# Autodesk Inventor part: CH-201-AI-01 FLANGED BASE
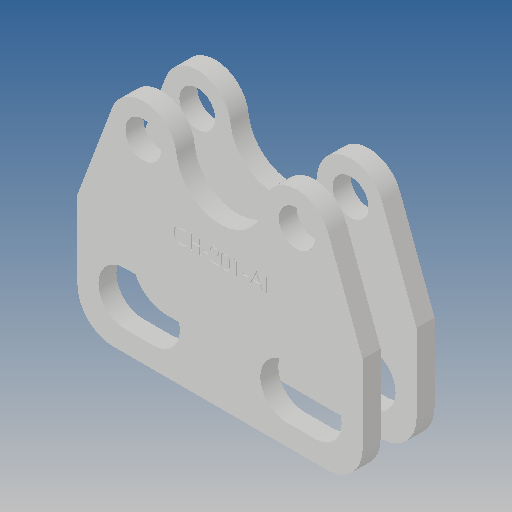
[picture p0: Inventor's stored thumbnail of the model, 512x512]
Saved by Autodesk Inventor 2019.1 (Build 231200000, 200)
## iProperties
Created: 2012-09
Part Number: CH-201-AI-01 FLANGED BASE
Material: Ogólny
Document SubType Name: Modeling
Designer: CADENGINEERING4
Density: 1 g/cm^3
Appearance: Domyślna
Author: CADENGINEERING4
Revision Number: ÈÎºÎ
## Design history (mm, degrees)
feature "ÇÐ³ý-À­Éì6[1]"
feature "ÇÐ³ý-À­Éì6[2]"
node "Bryła1"
node "Bryła2"
